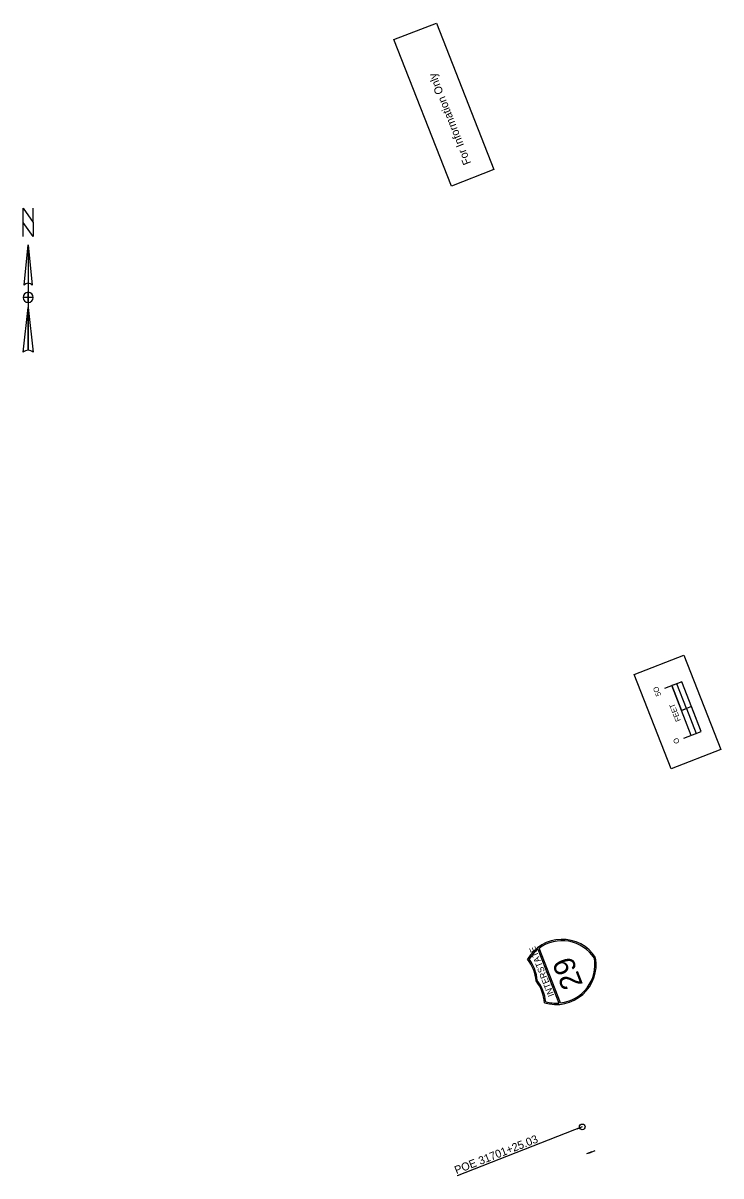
# Model space of a CAD drawing. Extents: x 14087837 to 14090046, y 8544369 to 8548535.
# Drawn here: x 14087837 to 14088491, y 8547454 to 8548535 of the extents above; entities that cross this region are included whole.
import ezdxf

# ---------------------------------------------------------------- set-up
doc = ezdxf.new("R2010")
doc.units = 0
for name, color, linetype in [('_CIVIL_CONSTRUCTION', 7, 'Continuous'), ('Default', 7, 'Continuous'), ('EXT_SNP', 7, 'Continuous'), ('Roadways', 7, 'Continuous'), ('Text', 7, 'Continuous'), ('Wetlands', 7, 'Continuous')]:
    doc.layers.add(name, color=color, linetype=linetype)

msp = doc.modelspace()

# ---------------------------------------------------------------- linework, layer by layer
at = {"layer": '_CIVIL_CONSTRUCTION'}
for p in [(14088361.3, 8547500.3), (14088244, 8547454.3)]:
    msp.add_line(p, (14088244, 8547454.3), dxfattribs=at)
msp.add_circle((14088361.3, 8547500.3), 2.67, dxfattribs=at)
at = {"layer": 'EXT_SNP'}
for p, q in [((14087842.1, 8548327.2), (14087845.9, 8548289.2)), ((14087842.1, 8548327.2), (14087842.1, 8548228.3)), ((14087838.3, 8548289.2), (14087838.3, 8548289.2)), ((14087838.4, 8548289.5), (14087839.2, 8548290.3)), ((14087842.1, 8548273), (14087842.1, 8548273)), ((14087837.3, 8548226.4), (14087842.1, 8548268.3)), ((14088319.8, 8547666.9), (14088339.5, 8547616.4)), ((14088340.8, 8547616.5), (14088320.8, 8547667.7))]:
    msp.add_line(p, q, dxfattribs=at)
for points in [[(14088238.7, 8548382.2), (14088184.9, 8548519.4), (14088224.7, 8548534.9), (14088278.4, 8548397.7)], [(14087846.9, 8548334.8), (14087837.3, 8548348.1), (14087837.3, 8548361.4), (14087846.9, 8548348.1)]]:
    msp.add_lwpolyline(points, close=True, dxfattribs=at)
for points in [[(14087837.3, 8548334.8), (14087837.3, 8548361.4), (14087846.9, 8548348.1), (14087846.9, 8548361.4)], [(14087838.3, 8548289.2), (14087842.1, 8548327.2), (14087842.1, 8548291.1)], [(14087846.9, 8548277.8), (14087842.1, 8548277.8), (14087842.1, 8548282.5)], [(14087842.1, 8548273), (14087842.1, 8548277.8), (14087837.3, 8548277.8)], [(14087842.1, 8548228.3), (14087842.1, 8548268.3), (14087846.9, 8548226.4)]]:
    msp.add_lwpolyline(points, dxfattribs=at)
for centre, radius, start, end in [((14087842.1, 8548277.8), 4.75, 90, 180), ((14087842.1, 8548286.3), 4.75, 90.0204, 143.1257), ((14087842.1, 8548286.3), 4.75, 36.8481, 90.0218), ((14087842.1, 8548277.8), 4.75, 0, 90), ((14087842.1, 8548277.8), 4.75, 180, 270), ((14087842.1, 8548277.8), 4.75, 270, 360), ((14087842.1, 8548221.4), 6.89, 89.9894, 133.619), ((14087842.1, 8548221.4), 6.89, 46.4021, 90.0006), ((14088342.4, 8547638.6), 37.5, 32.9199, 149.7139), ((14088342.4, 8547638.6), 36.2, 128.6461, 148.3869), ((14088342.4, 8547638.6), 36.2, 33.3124, 126.6295), ((14088280.6, 8547634.2), 37.5, 4.3918, 38.3739), ((14088280.6, 8547634.3), 38.7, 4.8083, 36.9438), ((14088336.9, 8547652.5), 37.5, 253.0518, 9.8458), ((14088337, 8547652.5), 36.2, 276.1362, 9.4533), ((14088288.6, 8547613.8), 37.5, 4.3918, 38.3739), ((14088288.6, 8547613.7), 38.7, 5.8219, 37.9574), ((14088336.9, 8547652.5), 36.2, 254.3787, 274.1194)]:
    msp.add_arc(centre, radius, start, end, dxfattribs=at)
at = {"layer": 'Roadways'}
for p, q in [((14088361.3, 8547500.2), (14088356.2, 8547498.2)), ((14088367.6, 8547475.8), (14088373.3, 8547478.1))]:
    msp.add_line(p, q, dxfattribs=at)
at = {"layer": 'Text'}
msp.add_line((14088463.7, 8547894.3), (14088454.4, 8547890.6), dxfattribs=at)
msp.add_line((14088463.7, 8547894.3), (14088454.4, 8547890.6), dxfattribs=at)
for points in [[(14088444.7, 8547835.8), (14088410.1, 8547924.3), (14088456.6, 8547942.5), (14088491.3, 8547854)], [(14088444.7, 8547835.8), (14088410.1, 8547924.3), (14088456.6, 8547942.5), (14088491.3, 8547854)], [(14088491.3, 8547854), (14088444.7, 8547835.8), (14088410.1, 8547924.3), (14088456.6, 8547942.5)], [(14088459, 8547892.4), (14088449.9, 8547915.7), (14088445.3, 8547913.9), (14088454.4, 8547890.6)], [(14088472.8, 8547871), (14088463.7, 8547894.3), (14088459, 8547892.4), (14088468.1, 8547869.1)]]:
    msp.add_lwpolyline(points, close=True, dxfattribs=at)
for points in [[(14088456.5, 8547864.6), (14088472.8, 8547871), (14088454.6, 8547917.5), (14088438.3, 8547911.1)], [(14088463.5, 8547867.3), (14088445.3, 8547913.9)]]:
    msp.add_lwpolyline(points, dxfattribs=at)
at = {"layer": 'Wetlands'}
msp.add_line((14088370.4, 8547477), (14088365.4, 8547475), dxfattribs=at)

# ---------------------------------------------------------------- texts
at = {"layer": '_CIVIL_CONSTRUCTION'}
for s, p in [('31701+25.03', (14088265.8, 8547464.6)), ('POE ', (14088243.4, 8547455.9))]:
    msp.add_text(s, height=7.5, rotation=21.3828, dxfattribs=at).set_placement(p)
at = {"layer": 'Default'}
msp.add_text('For Information Only', height=7.5, rotation=111.3828, dxfattribs=at).set_placement((14088257.2, 8548403.7))
at = {"layer": 'EXT_SNP'}
for s, height, p in [('INTERSTATE', 6, (14088335.2, 8547623.7)), ('29', 20, (14088362.2, 8547633.8))]:
    msp.add_text(s, height=height, rotation=111.3828, dxfattribs=at).set_placement(p)
at = {"layer": 'Text'}
for s, p in [('5O', (14088435.4, 8547905)), ('FEET', (14088453.8, 8547881.3)), ('O', (14088452.8, 8547860.5))]:
    msp.add_text(s, height=5, rotation=111.3828, dxfattribs=at).set_placement(p)

doc.saveas('drawing.dxf')
